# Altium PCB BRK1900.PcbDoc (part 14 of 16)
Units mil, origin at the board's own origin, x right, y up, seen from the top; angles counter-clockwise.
Board outline 8858.27 x 5905.51 mil, 10 copper layers (L1-TOP, L2-GND, L3-PWR, L4-GND, L5-PWR, L6-PWR, L7-GND, L8-SIG, L9-GND, L10-BOT), stack 48.824 mil thick; 456 components, 571 nets, 2296 pads, 2416 vias.
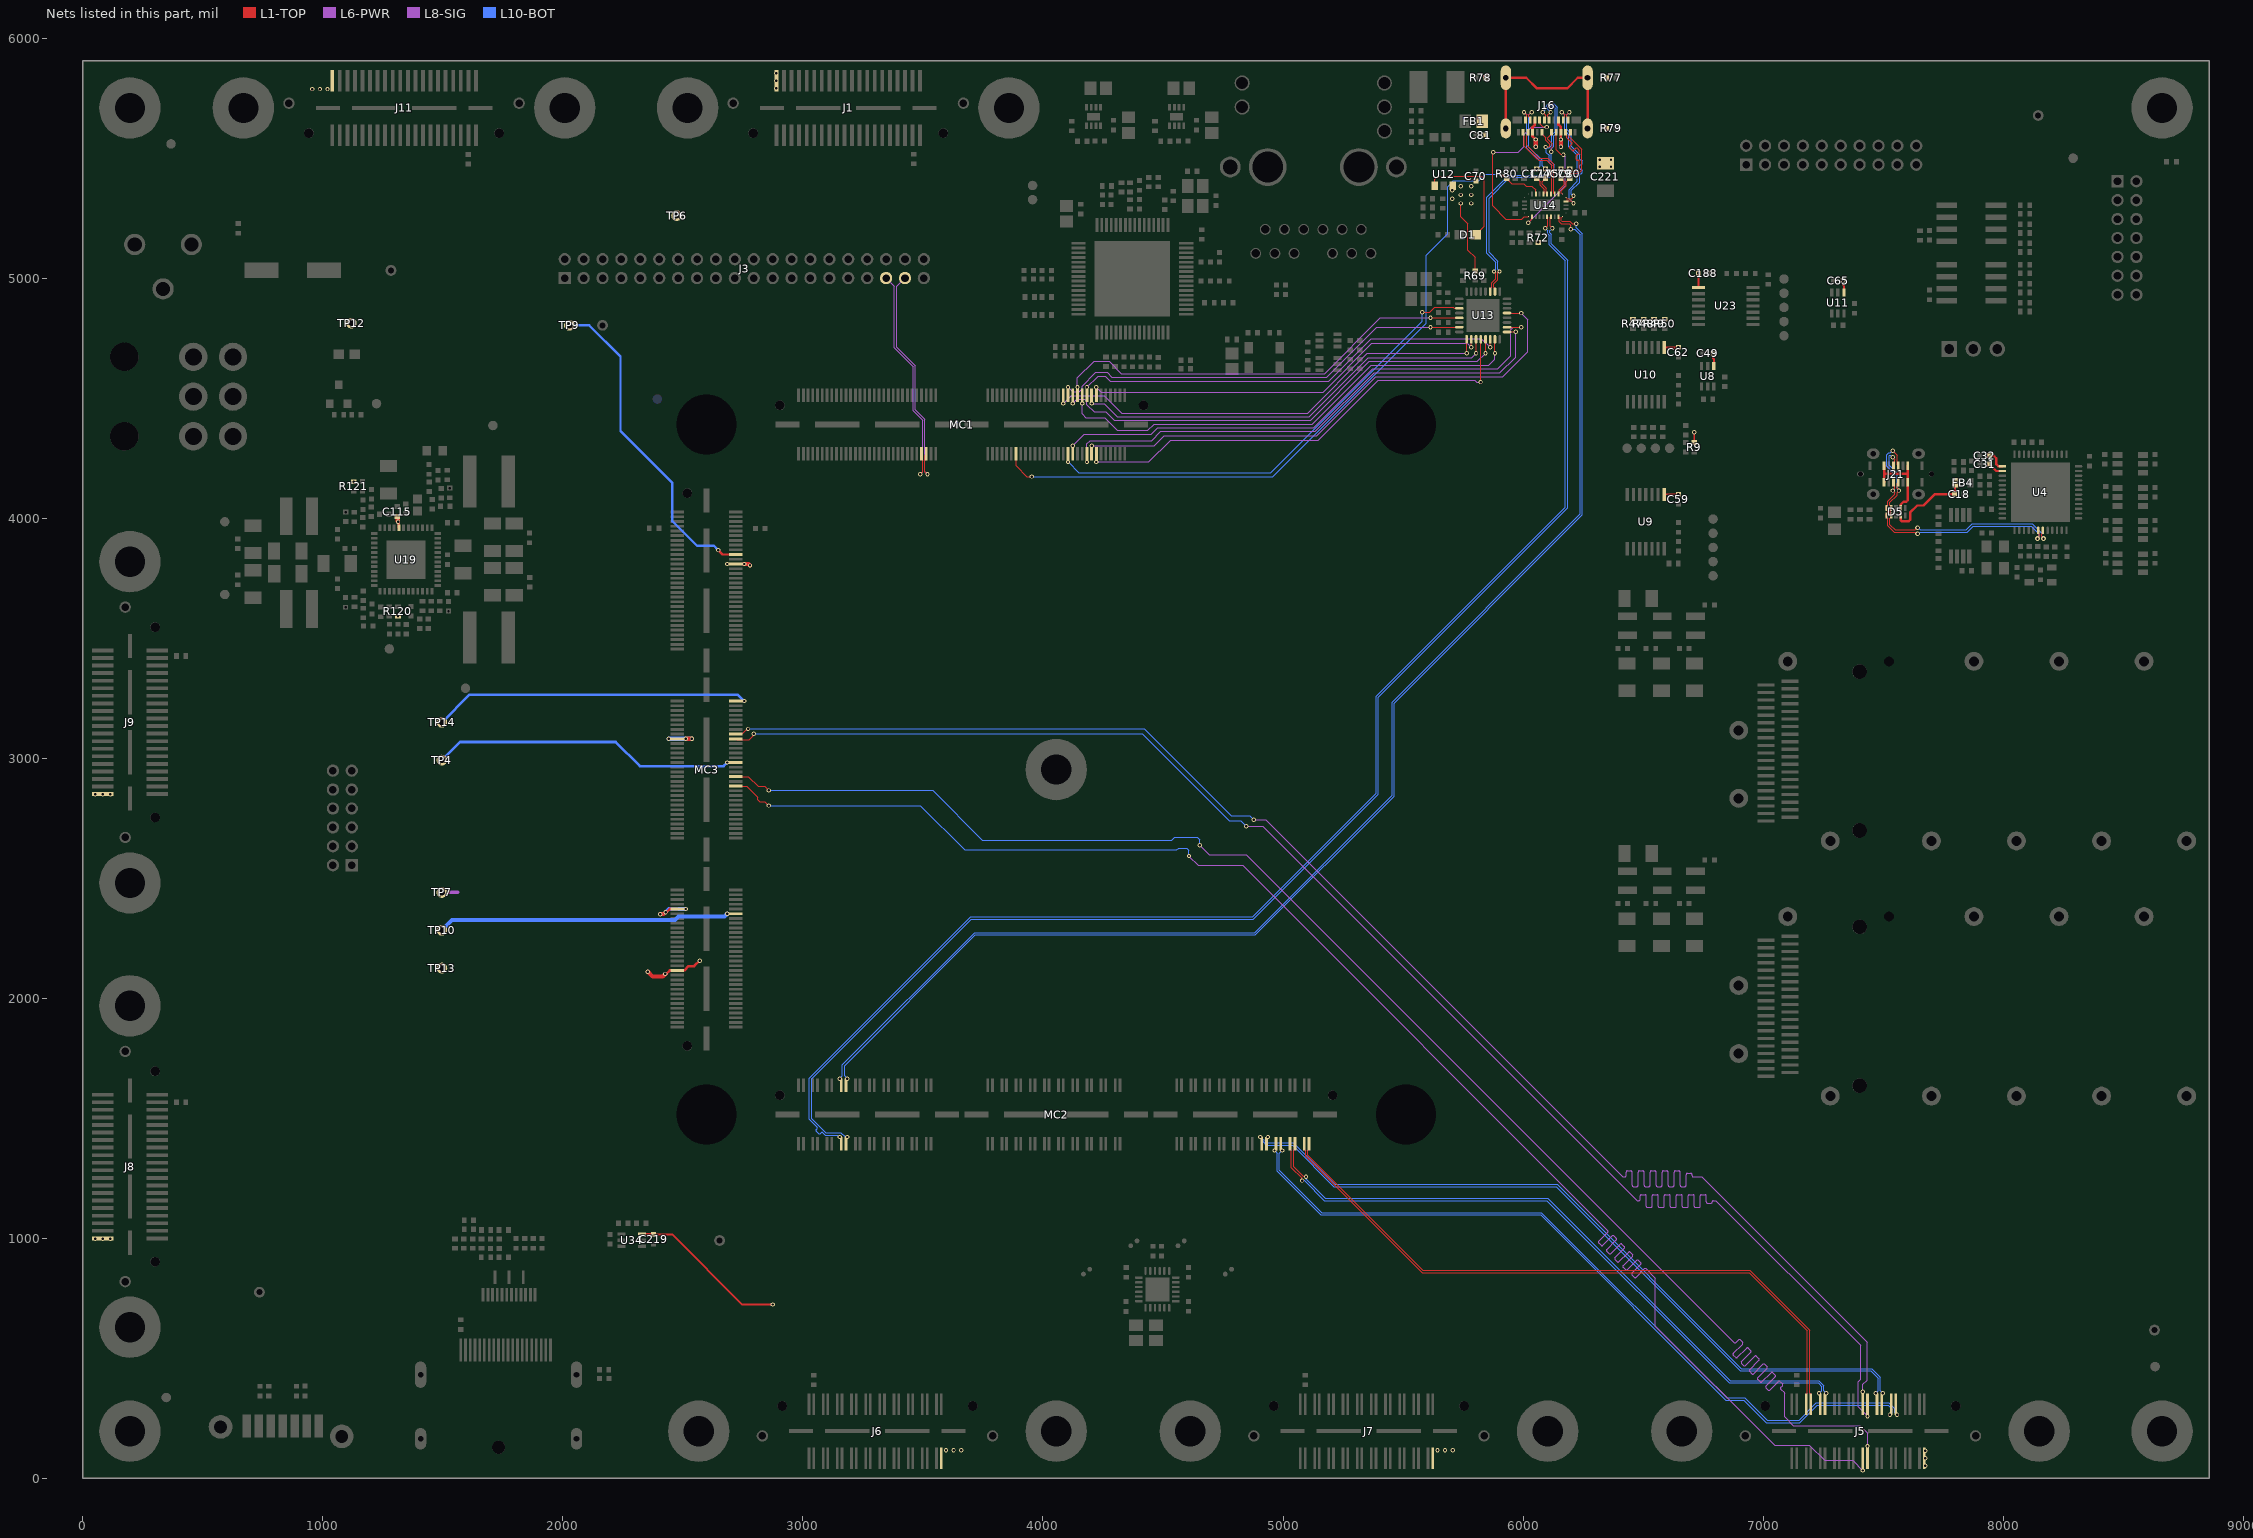
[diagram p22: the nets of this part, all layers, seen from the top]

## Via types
v1: diameter 18, hole 10, L1-TOP to L10-BOT, tented both sides, 2170 vias
v2: diameter 20, hole 10, L1-TOP to L10-BOT, tented both sides, 246 vias

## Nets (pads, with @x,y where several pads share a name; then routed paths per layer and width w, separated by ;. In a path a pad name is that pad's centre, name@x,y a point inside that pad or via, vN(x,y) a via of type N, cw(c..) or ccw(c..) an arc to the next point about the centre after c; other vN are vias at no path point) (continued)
SZG_PORTG_S6: J5.21 MC3.84 | length 6621.1
  L1-TOP w4: MC3.84@2720.08,2883.86 2765.75,2883.86 2812.48,2837.12 2812.48,2826.21 2819.36,2819.33 2841.77,2819.33 v1(2858.27,2802.83)
  L8-SIG w4: v1(4608.21,2592.58) 4647.58,2553.21 4831.88,2553.21 6334.28,1050.81 6352.66,1032.43 cw(c6349.27,1029.03) 6352.66,1025.64 6314.55,987.53 ccw(c6317.95,984.14) 6314.55,980.74 6324.74,970.56 ccw(c6328.13,973.95) 6331.52,970.56 6371.15,1010.18 cw(c6374.54,1006.79) 6377.94,1010.18 6388.12,1000 cw(c6384.72,996.61) 6388.12,993.21 6348.5,953.59 ccw(c6351.89,950.2) 6348.5,946.8 6358.68,936.62 ccw(c6362.07,940.01) 6365.47,936.62 6405.09,976.24 cw(c6408.48,972.85) 6411.88,976.24 6422.06,966.06 cw(c6418.66,962.67) 6422.06,959.27 6382.44,919.65 ccw(c6385.83,916.25) 6382.44,912.86 6392.62,902.68 ccw(c6396.01,906.07) 6399.41,902.68 6439.03,942.3 cw(c6442.42,938.91) 6445.82,942.3 6456,932.12 cw(c6452.61,928.72) 6456,925.33 6416.38,885.71 ccw(c6419.77,882.31) 6416.38,878.92 6426.56,868.74 ccw(c6429.95,872.13) 6433.35,868.74 6472.97,908.36 cw(c6476.36,904.97) 6479.76,908.36 6489.94,898.18 cw(c6486.55,894.78) 6489.94,891.39 6453.45,854.89 ccw(c6456.84,851.5) 6453.45,848.11 6463.63,837.92 ccw(c6467.02,841.32) 6470.42,837.92 6505.4,872.9 cw(c6508.79,869.51) 6512.18,872.9 6544.91,840.18 6551.18,833.91 6551.18,634.47 7047.86,137.8 7192.91,137.8 7255.91,74.8 7372.97,74.8 v1(7414.91,32.86)
  L10-BOT w4: v1(2858.27,2802.83) 3488.86,2802.83 3673.92,2617.77 4557.51,2617.77 4565.29,2625.55 4598.57,2625.55 4608.21,2615.91 v1(4608.21,2592.58)
SZG_PORTG_S7: J5.22 MC3.106 | length 6623
  L1-TOP w4: MC3.106@2720.08,3100.39 2723.98,3104.3 2749.81,3104.3 2764.88,3119.37 2768.97,3119.37 v1(2771.65,3122.05)
  L8-SIG w5: v1(4877.95,2744.09) 4926.99,2744.09 6415.17,1255.91 6421.26,1255.91 6423.76,1255.91 ccw(c6423.76,1260.91) 6428.76,1260.91 6428.76,1275.91 cw(c6433.76,1275.91) 6433.76,1280.91 6448.76,1280.91 cw(c6448.76,1275.91) 6453.76,1275.91 6453.76,1220.8 ccw(c6458.76,1220.8) 6458.76,1215.8 6473.76,1215.8 ccw(c6473.76,1220.8) 6478.76,1220.8 6478.76,1275.91 cw(c6483.76,1275.91) 6483.76,1280.91 6498.76,1280.91 cw(c6498.76,1275.91) 6503.76,1275.91 6503.76,1220.8 ccw(c6508.76,1220.8) 6508.76,1215.8 6523.76,1215.8 ccw(c6523.76,1220.8) 6528.76,1220.8 6528.76,1275.91 cw(c6533.76,1275.91) 6533.76,1280.91 6548.76,1280.91 cw(c6548.76,1275.91) 6553.76,1275.91 6553.76,1220.8 ccw(c6558.76,1220.8) 6558.76,1215.8 6573.76,1215.8 ccw(c6573.76,1220.8) 6578.76,1220.8 6578.76,1275.91 cw(c6583.76,1275.91) 6583.76,1280.91 6598.76,1280.91 cw(c6598.76,1275.91) 6603.76,1275.91 6603.76,1220.8 ccw(c6608.76,1220.8) 6608.76,1215.8 6623.76,1215.8 ccw(c6623.76,1220.8) 6628.76,1220.8 6628.76,1275.91 cw(c6633.76,1275.91) 6633.76,1280.91 6648.76,1280.91 cw(c6648.76,1275.91) 6653.76,1275.91 6653.76,1220.8 ccw(c6658.76,1220.8) 6658.76,1215.8 6673.76,1215.8 ccw(c6673.76,1220.8) 6678.76,1220.8 6678.76,1265.73 cw(c6683.76,1265.73) 6683.76,1270.73 6698.76,1270.73 cw(c6698.76,1265.73) 6703.76,1265.73 6703.76,1260.91 ccw(c6708.76,1260.91) 6708.76,1255.91 6743.94,1255.91 7433.07,566.77 7433.07,409.45 7414.91,391.29 v1(7414.91,360.84)
  L10-BOT w4: v1(2771.65,3122.05) 4421.54,3122.05 4783.37,2760.22 4861.83,2760.22 v1(4877.95,2744.09)
SZG_PORTG_S8: J5.23 MC3.88 | length 6621.1
  L1-TOP w4: MC3.88@2720.08,2923.23 2773.31,2923.23 2814.21,2882.32 2841.77,2882.32 v1(2858.27,2865.83)
  L8-SIG w4: v1(4652.75,2637.12) 4692.12,2597.75 4847.75,2597.75 6878.26,567.24 6879.68,565.82 ccw(c6883.07,569.22) 6886.46,565.82 6897.35,576.71 cw(c6900.75,573.32) 6904.14,576.71 6914.32,566.53 cw(c6910.93,563.14) 6914.32,559.74 6875.32,520.74 ccw(c6878.71,517.34) 6875.32,513.95 6885.5,503.77 ccw(c6888.9,507.16) 6892.29,503.77 6931.3,542.77 cw(c6934.69,539.38) 6938.08,542.77 6948.27,532.59 cw(c6944.87,529.2) 6948.27,525.8 6909.26,486.8 ccw(c6912.66,483.4) 6909.26,480.01 6919.44,469.83 ccw(c6922.84,473.22) 6926.23,469.83 6965.24,508.83 cw(c6968.63,505.44) 6972.02,508.83 6982.21,498.65 cw(c6978.81,495.25) 6982.21,491.86 6943.2,452.86 ccw(c6946.6,449.46) 6943.2,446.07 6953.39,435.89 ccw(c6956.78,439.28) 6960.17,435.89 6999.18,474.89 cw(c7002.57,471.5) 7005.97,474.89 7016.15,464.71 cw(c7012.75,461.31) 7016.15,457.92 6977.14,418.91 ccw(c6980.54,415.52) 6977.14,412.13 6987.33,401.94 ccw(c6990.72,405.34) 6994.11,401.94 7033.12,440.95 cw(c7036.51,437.55) 7039.91,440.95 7050.09,430.77 cw(c7046.69,427.37) 7050.09,423.98 7011.09,384.97 ccw(c7014.48,381.58) 7011.08,378.19 7021.27,368 ccw(c7024.66,371.4) 7028.06,368 7063.75,403.69 cw(c7067.14,400.3) 7070.53,403.69 7080.72,393.51 cw(c7077.32,390.12) 7080.72,386.72 7073.14,379.15 ccw(c7076.53,375.75) 7073.14,372.36 7086.92,358.58 7090.55,354.95 7090.55,255.91 7125.98,220.47 7401.57,220.47 7434.6,187.45 v1(7434.6,134.86)
  L10-BOT w4: v1(2858.27,2865.83) 3539.88,2865.83 3747.89,2657.81 4535.77,2657.81 4548.22,2670.27 4642.94,2670.27 4652.75,2660.45 v1(4652.75,2637.12)
SZG_PORTG_S9: J5.24 MC3.104 | length 6623
  L1-TOP w4: MC3.104@2720.08,3080.71 2723.58,3077.21 2775.96,3077.21 2792.6,3093.84 2792.6,3099.68 v1(2795.28,3102.36)
  L8-SIG w5: v1(4846.46,2716.54) 4915.57,2716.54 6474.63,1157.48 6480.31,1157.48 6482.82,1157.48 ccw(c6482.82,1162.48) 6487.82,1162.48 6487.82,1177.48 cw(c6492.82,1177.48) 6492.82,1182.48 6507.82,1182.48 cw(c6507.82,1177.48) 6512.82,1177.48 6512.82,1134 ccw(c6517.82,1134) 6517.82,1129 6532.82,1129 ccw(c6532.82,1134) 6537.82,1134 6537.82,1177.48 cw(c6542.82,1177.48) 6542.82,1182.48 6557.82,1182.48 cw(c6557.82,1177.48) 6562.82,1177.48 6562.82,1134 ccw(c6567.82,1134) 6567.82,1129 6582.82,1129 ccw(c6582.82,1134) 6587.82,1134 6587.82,1177.48 cw(c6592.82,1177.48) 6592.82,1182.48 6607.82,1182.48 cw(c6607.82,1177.48) 6612.82,1177.48 6612.82,1134 ccw(c6617.82,1134) 6617.82,1129 6632.82,1129 ccw(c6632.82,1134) 6637.82,1134 6637.82,1177.48 cw(c6642.82,1177.48) 6642.82,1182.48 6657.82,1182.48 cw(c6657.82,1177.48) 6662.82,1177.48 6662.82,1134 ccw(c6667.82,1134) 6667.82,1129 6682.82,1129 ccw(c6682.82,1134) 6687.82,1134 6687.82,1177.48 cw(c6692.82,1177.48) 6692.82,1182.48 6707.82,1182.48 cw(c6707.82,1177.48) 6712.82,1177.48 6712.82,1134 ccw(c6717.82,1134) 6717.82,1129 6732.82,1129 ccw(c6732.82,1134) 6737.82,1134 6737.82,1177.48 cw(c6742.82,1177.48) 6742.82,1182.48 6757.82,1182.48 cw(c6757.82,1177.48) 6762.82,1177.48 6762.82,1151.76 ccw(c6767.82,1151.76) 6767.82,1146.76 6782.82,1146.76 ccw(c6782.82,1151.76) 6787.82,1151.76 6787.82,1152.48 cw(c6792.82,1152.48) 6792.82,1157.48 6803.15,1157.48 6803.39,1157.48 7405.51,555.36 7405.51,413.39 7395.52,403.4 7395.52,297.91 v1(7434.6,258.84)
  L10-BOT w4: v1(2795.28,3102.36) 4413.39,3102.36 4776.81,2738.94 4824.05,2738.94 v1(4846.46,2716.54)
SZG_PORTG_TX0N: J5.8 MC2.120 | length 2752.4
  L1-TOP w3.3: MC2.120@5108.27,1394.09 5108.27,1371.46 5102.92,1366.11 5102.92,1345.89 5582.68,866.14 6944.88,866.14 7193.03,617.99 7193.03,354.36 7198.38,349.02 J5.8@7198.38,309.84
SZG_PORTG_TX0P: J5.6 MC2.118 | length 2752.4
  L1-TOP w3.3: MC2.118@5088.58,1394.09 5088.58,1371.46 5093.92,1366.11 5093.92,1342.17 5578.95,857.14 6941.15,857.14 7184.03,614.26 7184.03,354.36 7178.69,349.02 J5.6@7178.69,309.84
SZG_PORTG_TX1N: J5.12 MC2.116 | length 2727.7
  L1-TOP w3.3: MC2.116@5049.21,1394.09 5049.21,1371.46 5043.87,1366.11 5043.87,1298.65 5083.99,1258.53 5093.89,1258.53 v1(5095.5,1256.92)
  L10-BOT w3.3: v1@5094.55,1257.87 v1(5095.5,1256.92) 5094.49,1255.91 5094.49,1248.03 5176.04,1166.48 5669.29,1166.48 6102.15,1166.48 6862,406.64 7232.07,406.64 7252.09,386.62 7252.09,365.22 v1(7262.47,354.84)
SZG_PORTG_TX1P: J5.10 MC2.114 | length 2727.7
  L1-TOP w3.3: MC2.114@5029.53,1394.09 5029.53,1371.46 5034.87,1366.11 5034.87,1294.92 5077.62,1252.17 5077.62,1242.27 v1(5079.24,1240.65)
  L10-BOT w3.3: v1@5078.28,1241.61 v1(5079.24,1240.65) 5080.25,1241.67 5088.12,1241.67 5172.31,1157.48 5669.29,1157.48 6098.43,1157.48 6858.27,397.64 7228.35,397.64 7243.09,382.9 7243.09,365.22 v1(7232.71,354.84)
SZG_PORTG_TX2N: J5.32 MC2.112 | length 3152.6
  L10-BOT w3.3: v1(4996.06,1366.09) 4984.81,1354.85 4984.81,1282.9 5160.29,1107.43 6076.27,1107.43 6848.66,335.03 6922.77,335.03 7015.96,241.85 7149.24,241.85 7221.96,314.56 7523.77,314.56 7547.36,290.96 7547.36,274.13 7556.65,264.84 v1(7557.74,264.84)
SZG_PORTG_TX2P: J5.30 MC2.110 | length 3152.6
  L10-BOT w3.3: v1(4964.57,1366.09) 4975.81,1354.85 4975.81,1279.17 5156.56,1098.43 6072.54,1098.43 6844.93,326.03 6919.04,326.03 7012.23,232.85 7152.97,232.85 7225.68,305.56 7520.04,305.56 7538.36,287.24 7538.36,274.13 7529.08,264.84 v1(7527.98,264.84)
SZG_PORTG_TX3N: J5.28 MC2.108 | length 3062.7
  L10-BOT w3.3: v1(4937.01,1422.09) 4925.76,1410.85 4925.76,1405.51 4933.63,1397.64 5043.31,1397.64 5215.95,1225 5460.63,1225 6137.48,1225 6141.2,1225 6908.38,457.82 7452.55,457.82 7488.31,422.06 7488.31,365.22 v1(7498.69,354.84)
SZG_PORTG_TX3P: J5.26 MC2.106 | length 3062.7
  L10-BOT w3.3: v1(4905.51,1422.09) 4916.76,1410.85 4916.76,1401.78 4929.91,1388.64 5039.58,1388.64 5212.22,1216 6137.48,1216 6904.66,448.82 7448.82,448.82 7479.31,418.33 7479.31,365.22 v1(7468.93,354.84)
USB_CC1: J16.A5 U14.2 | length 494.2
  L1-TOP w5: v1(6021.41,5230.32) 6035.82,5244.74 6035.82,5254.56 U14.2@6037.26,5256 ; J16.A5@6137.8,5607.09 6137.8,5535.4 6156.73,5516.46 6165.65,5516.46 v1(6167.86,5514.25)
  L8-SIG w5: v1(6021.41,5230.32) 6176.18,5385.09 6176.18,5505.93 v1(6167.86,5514.25)
USB_CC2: J16.B5 U14.1 | length 746.2
  L1-TOP w5: v1(5876,5524) 5872.61,5520.61 5872.61,5300.39 5927.01,5245.99 5995.08,5245.99 6005.09,5256 U14.1@6021.51,5256 ; J16.B5@6068.9,5658.27 6072.3,5654.86 6072.3,5639.97 6082.43,5629.85 6097.71,5629.85 v1(6098.46,5629.1)
  L8-SIG w5: v1(5876,5524) 5979,5524 6003,5548 6003,5598 6034.1,5629.1 v1(6098.46,5629.1)
USB_CLKOUT: MC1.93 U13.1 | length 1885.1
  L1-TOP w4.55: v1(5764.65,4686.28) U13.1@5764.65,4745.06
  L8-SIG w4.05: v1(4084.65,4477.42) 4117.15,4509.92 4256.08,4509.92 4328.29,4437.71 5102.59,4437.71 5351.16,4686.28 v1(5764.65,4686.28)
USB_DATA0: MC1.105 U13.3 | length 1792.1
  L1-TOP w4.55: v1(5804.02,4686.28) U13.3@5804.02,4745.06
  L8-SIG w4.05: v1(4202.76,4477.42) 4254.58,4477.42 4309.53,4422.47 5108.9,4422.47 5353.99,4667.56 5785.3,4667.56 v1(5804.02,4686.28)
USB_DATA1: MC1.108 U13.4 | length 1923.4
  L1-TOP w4.55: v1(5822.83,4566.93) 5823.27,4567.37 5823.27,4744.62 U13.4@5823.71,4745.06
  L8-SIG w4.05: v1(4222.44,4234.11) 4441.11,4234.11 4531.31,4324.31 5145.78,4324.31 5396.41,4574.94 5799.07,4574.94 5807.09,4566.93 v1(5822.83,4566.93)
USB_DATA2: MC1.97 U13.5 | length 1945
  L1-TOP w4.55: v1(5843.39,4686.28) U13.5@5843.39,4745.06
  L8-SIG w4.05: v1(4124.02,4477.42) 4141.4,4494.8 4174.76,4494.8 4183,4486.56 4183,4472.64 4212.64,4443 4261,4443 4296.3,4407.7 5115.02,4407.7 5360.11,4652.78 5809.9,4652.78 v1(5843.39,4686.28)
USB_DATA3: MC1.103 U13.6 | length 1830.4
  L1-TOP w4.55: v1(5863.08,4711.28) U13.6@5863.08,4745.06
  L8-SIG w4.05: v1(4183.07,4545.42) 4229.65,4592 4258.39,4592 4279.53,4570.87 5189.34,4570.87 5366.51,4748.03 5826.32,4748.03 v1(5863.08,4711.28)
USB_DATA4: MC1.101 U13.7 | length 1996
  L1-TOP w4.55: v1(5882.76,4686.28) U13.7@5882.76,4745.06
  L8-SIG w4.05: v1(4163.39,4477.42) 4163.39,4434.6 4178.99,4419 4257,4419 4309.86,4366.14 4437.14,4366.14 4463,4392 5121.52,4392 5366.61,4637.08 5857.56,4637.08 5882.76,4662.29 v1(5882.76,4686.28)
USB_DATA5: MC1.104 U13.9 | length 2151.6
  L1-TOP w4.55: U13.9@5932.96,4775.57 5968.17,4775.57 v1(5968.74,4776.13)
  L8-SIG w4.05: v1(4183.07,4234.11) 4183.07,4309.07 4196.43,4322.43 4453,4322.43 4491.57,4361 5134.36,4361 5379.45,4606.08 5903.65,4606.08 5968.74,4671.18 v1(5968.74,4776.13)
USB_DATA6: MC1.98 U13.10 | length 2194.3
  L1-TOP w4.55: U13.10@5932.96,4795.25 v1(5991.74,4795.25)
  L8-SIG w4.05: v1(4124.02,4302.11) 4170.9,4349 4451,4349 4479,4377 5127.74,4377 5372.82,4622.08 5893.67,4622.08 5948.82,4677.23 5948.82,4785.62 5958.45,4795.25 v1(5991.74,4795.25)
USB_DATA7: MC1.106 U13.13 | length 2210.5
  L1-TOP w4.55: U13.13@5932.96,4854.31 v1(5991.74,4854.31)
  L8-SIG w4.05: v1(4202.76,4302.11) 4463,4302.11 4504.89,4344 5141.4,4344 5386.49,4589.08 5915.79,4589.08 6019.69,4692.98 6019.69,4826.36 v1(5991.74,4854.31)
USB_DIR: MC1.95 U13.31 | length 1773.3
  L1-TOP w4.55: v1(5614.14,4795.25) U13.31@5734.14,4795.25
  L8-SIG w4.05: v1(4104.33,4545.42) 4123.75,4526 4151,4526 4163,4538 4163,4550 4220,4607 4267.02,4607 4287.4,4586.61 5181.47,4586.61 5390.11,4795.25 v1(5614.14,4795.25)
USB_DN: J16.A7 J16.B7 U13.19 | length 1230.6
  L1-TOP w4.05: U13.19@5863.08,4943.87 5863.08,4955.68 5868.42,4961.02 5868.42,4979.57 5885.83,4996.98 5885.83,5023.62 5881.89,5027.56 v1(5878.83,5027.56) ; J16.A7@6078.74,5607.09 6078.74,5599.99 6093.93,5584.81 6093.93,5574.08 6108,5560 6111.51,5556.49 6111.51,5548.49 6109.11,5546.1 v1(6093.48,5546.1) ; J16.B7@6108.27,5658.27 6108.27,5666.12 6102.93,5671.46 6102.93,5679.55 v1(6114.41,5691.04)
  L10-BOT w4.05: v1(5878.83,5027.56) 5878.83,5029.91 5885.83,5036.91 5885.83,5066.93 5849,5103.76 5849,5307.08 5849,5336.09 5940.91,5428 6106,5428 6120,5442 6120,5469.33 6108.48,5480.86 6108.48,5510.79 6096.48,5522.79 6096.48,5543.1 6109.11,5543.1 6119.5,5553.49 6119.5,5596.5 6133,5610 6133,5708 6123.52,5717.48 6108.95,5717.48 6102.48,5711 6102.48,5702.98 v1(6114.41,5691.04)
USB_DP: J16.A6 J16.B6 U13.18 | length 1248.1
  L1-TOP w4.05: U13.18@5882.76,4943.87 5882.76,4955.9 5877.42,4961.24 5877.42,4975.85 5894.83,4993.25 5894.83,5023.62 5898.76,5027.56 v1(5901.83,5027.56) ; v1(6081.54,5691.04) 6093.93,5678.66 6093.93,5671.26 6088.58,5665.91 J16.B6@6088.58,5658.27 ; v1(6117.48,5526.1) 6117.48,5541.74 6117.87,5542.13 6120.51,5544.77 6120.51,5560.22 6117.87,5562.86 6102.93,5577.8 6102.93,5584.15 6118.11,5599.33 J16.A6@6118.11,5607.09
  L10-BOT w4.05: v1(5901.83,5027.56) 5901.83,5029.91 5894.83,5036.91 5894.83,5070.66 5858,5107.48 5858,5255.53 5858,5332.37 5944.63,5419 6109.73,5419 6112.36,5421.64 6129,5438.27 6129,5473.06 6117.48,5484.58 v1(6117.48,5526.1) 6117.48,5538.74 6128.5,5549.76 6128.5,5592.77 6142,5606.27 6142,5711.73 6127.25,5726.48 6105.23,5726.48 6093.48,5714.73 6093.48,5702.98 v1(6081.54,5691.04)
USB_JTAG_DN: D5.5 D5.6 J21.A7 J21.B7 U4.6 | length 1213.9
  L1-TOP w4: v1(7539.45,4280.49) 7557.77,4262.18 7557.77,4235.4 7558.71,4234.46 7558.71,4221.83 J21.B7@7562.61,4217.93 ; J21.A7@7542.93,4149.82 7546.83,4145.91 7546.83,4133.29 7547.77,4132.35 7547.77,4124.27 7540.11,4116.61 7539.45,4116.61 7539.45,4113.59 7547.45,4105.59 7547.45,4099.28 7518.24,4070.07 7518.24,4053.87 7513.4,4049.03 7513.4,4034.27 7518.23,4029.44 7518.24,4023.35 7513.4,4018.52 7513.4,4003.76 7518.24,3998.91 7518.24,3969.11 7545.19,3942.16 7632.98,3942.16 7640.48,3934.66 v2(7643.32,3934.66) ; v2(8142.54,3914.8) 8142.54,3917.64 8150.13,3925.23 8150.13,3933.33 8145.29,3938.18 U4.6@8145.29,3949.42
  L10-BOT w4: v1(7539.45,4114.93) 7539.45,4116.27 7547.45,4124.27 7547.45,4182.41 7514.4,4215.47 7514.4,4263.79 7522.6,4271.99 7530.11,4271.99 7538.61,4280.49 v1(7539.45,4280.49) ; v2(7643.32,3934.66) 7646.17,3934.66 7653.67,3942.16 7850.79,3942.16 7874.88,3966.26 8116.54,3966.26 8150.04,3932.76 8150.04,3925.14 8142.54,3917.64 v2(8142.54,3914.8)
USB_JTAG_DP: D5.4 D5.7 J21.A6 J21.B6 U4.7 | length 1165.4
  L1-TOP w4: v1(7539.45,4253.49) 7539.45,4252.47 7547.77,4244.15 7547.77,4235.4 7546.83,4234.46 7546.83,4221.83 J21.B6@7542.93,4217.93 ; J21.A6@7562.61,4149.82 7558.71,4145.91 7558.71,4133.29 7557.77,4132.35 7557.77,4124.27 7565.45,4116.59 7565.45,4113.59 7557.45,4105.59 7557.45,4095.13 7528.24,4065.93 7528.24,4053.87 7533.09,4049.03 7533.09,4034.27 7528.26,4029.44 7528.24,4023.35 7533.09,4018.52 7533.09,4003.76 7528.24,3998.91 7528.24,3973.25 7549.33,3952.16 7632.98,3952.16 7640.48,3959.66 v2(7643.32,3959.66) ; U4.7@8164.98,3949.42 8164.98,3938.18 8160.13,3933.33 8160.13,3925.14 8167.54,3917.73 v2(8167.54,3914.8)
  L10-BOT w4: v1(7539.45,4253.49) 7538.61,4253.49 7530.11,4261.99 7526.74,4261.99 7524.4,4259.65 7524.4,4219.61 7557.45,4186.56 7557.45,4124.27 7565.45,4116.27 v1(7565.45,4114.93) ; v2(7643.32,3959.66) 7646.17,3959.66 7653.67,3952.16 7846.64,3952.16 7870.74,3976.26 8120.69,3976.26 8160.04,3936.9 8160.04,3925.14 8167.54,3917.64 v2(8167.54,3914.8)
USB_NXT: MC1.107 U13.2 | length 1695.4
  L1-TOP w4.55: v1(5784.34,4711.28) U13.2@5784.34,4745.06
  L8-SIG w4.05: v1(4222.44,4545.42) 4242.86,4525 5166.81,4525 5370.16,4728.35 5767.27,4728.35 v1(5784.34,4711.28)
USB_RESET_B: MC1.96 U13.27 | length 1959.4
  L1-TOP w4.55: v1(5579.71,4858.28) 5611.48,4858.28 5632.61,4879.41 5708.61,4879.41 5714.02,4873.99 U13.27@5734.14,4873.99
  L10-BOT w4.55: v1(4104.33,4234.11) 4149.44,4189 4949.19,4189 5579.71,4819.52 v1(5579.71,4858.28)
USB_SHELL: C81.2 FB1.1 J16.M1 J16.M2 J16.M3 J16.M4 R77.1 R78.1 R79.1 | length 798.8
  L1-TOP w10: J16.M2@5928.35,5623.23 J16.M3@5928.35,5834.25 6013.08,5834.25 6057.23,5790.1 6183.55,5790.1 6227.7,5834.25 J16.M4@6268.5,5834.25 J16.M1@6268.5,5623.23
USB_SSRX_N: MC2.15 U14.10 | length 5617.3
  L1-TOP w4.05: U14.10@6163.24,5256 6159.87,5252.63 6159.87,5239 6162.87,5236 6195.05,5236 6203.02,5228.02 6205.36,5225.68 v1(6221.69,5225.68)
  L10-BOT w4.05: v1(3185.04,1665.4) 3173.79,1676.65 3173.79,1719 3718.57,2263.78 4884.85,2263.78 5463.02,2841.95 5463.02,3229.81 6247,4013.8 6247,5184.05 6221.69,5209.36 v1(6221.69,5225.68)
USB_SSRX_P: MC2.13 U14.9 | length 5617.3
  L1-TOP w4.05: U14.9@6147.5,5256 6150.87,5252.63 6150.87,5235.27 6159.14,5227 6191.32,5227 6199,5219.32 v1(6199,5203)
  L10-BOT w4.05: v1(3153.54,1665.4) 3164.79,1676.65 3164.79,1722.73 3714.84,2272.78 4881.12,2272.78 5454.02,2845.67 5454.02,3233.54 6238,4017.53 6238,5180.32 6215.32,5203 v1(6199,5203)
USB_SSRXN1: J16.B10 U14.14 | length 503.9
  L1-TOP w4.05: v1(6161.02,5691.04) 6172.67,5679.4 6172.67,5671.67 6167.32,5666.33 J16.B10@6167.32,5658.27 ; U14.14@6178.99,5318.99 6182.37,5322.37 6199.77,5322.37 v1(6210.05,5312.09)
  L10-BOT w4.05: v1(6161.02,5691.04) 6172.46,5679.6 6172.46,5615.81 6190.64,5597.64 6190.64,5546.36 6226,5511 6226,5402.73 6192,5368.73 6192,5330.14 v1(6210.05,5312.09)
USB_SSRXN2: J16.A10 U14.18 | length 327.7
  L1-TOP w4.05: J16.A10@6019.69,5607.09 6019.69,5598.83 6014.34,5593.49 6014.34,5553.66 6067.96,5500.04 6102.52,5500.04 6128.37,5474.19 6128.37,5353.86 U14.18@6131.75,5350.49
USB_SSRXP1: J16.B11 U14.15 | length 501.8
  L1-TOP w4.05: U14.15@6178.99,5334.74 6182.37,5331.37 6201.76,5331.37 v1@6210.05,5339.65 ; J16.B11@6187.01,5658.27 6187.01,5666.25 6181.67,5671.6 6181.67,5679.81 v1(6192.89,5691.04)
  L10-BOT w4.05: v1(6192.89,5691.04) 6181.46,5679.6 6181.46,5619.54 6197,5604 6199.64,5601.36 6199.64,5550.09 6235,5514.73 6235,5502 6235,5495.85 6238.81,5492.04 6243.19,5492.04 6247,5488.23 6247,5476.8 6243.19,5472.99 6238.81,5472.99 6235,5469.18 6235,5457.75 6238.81,5453.94 6243.19,5453.94 6247,5450.13 6247,5438.7 6243.19,5434.89 6238.81,5434.89 6235,5431.08 6235,5410 6235,5399 6201,5365 6201,5348.69 v1@6210.05,5339.65
  other v1: 6210.05,5342.65
USB_SSRXP2: J16.A11 U14.19 | length 327.7
  L1-TOP w4.05: J16.A11@6000,5607.09 6000,5598.96 6005.34,5593.62 6005.34,5549.93 6055.27,5500 6064.23,5491.04 6098.79,5491.04 6119.37,5470.46 6119.37,5353.86 U14.19@6116,5350.49
USB_SSTX_N: MC2.16 U14.7 | length 5969.5
  L1-TOP w4.05: U14.7@6116,5256 6112.63,5252.63 6112.63,5215.37 v1@6121,5207
  L10-BOT w4.05: v1(3185.04,1422.09) 3182.37,1424.76 3173.54,1424.76 3158.6,1439.7 3095.3,1439.7 3036,1499 3036,1664 3702,2330 4876.73,2330 5397,2850.27 5397,3254.35 6185,4042.35 6185,5075 6117,5143 6117,5182.63 6111.72,5187.91 6111.72,5196.62 6121,5205.9 v1@6121,5207
  other v1: 6122.1,5207
USB_SSTX_P: MC2.14 U14.6 | length 5969.5
  L1-TOP w4.05: v1@6093.44,5207 6103.63,5217.19 6103.63,5252.63 U14.6@6100.25,5256
  L10-BOT w4.05: v1(3153.54,1422.09) 3151.22,1422.09 3143.32,1430 3092.27,1430 3083.97,1438.3 3082.54,1439.73 ccw(c3079.14,1436.33) 3075.74,1439.73 3072.7,1436.7 cw(c3069.3,1440.1) 3065.9,1436.7 3055.7,1446.9 cw(c3059.1,1450.31) 3055.7,1453.71 3058.73,1456.74 ccw(c3055.33,1460.14) 3058.73,1463.54 3043.8,1478.48 3042.36,1479.91 3036.64,1485.64 3027,1495.27 3027,1667.73 3698.27,2339 4873,2339 5388,2854 5388,3258.08 6176,4046.08 6176,5071.27 6108,5139.27 6108,5178.9 6102.72,5184.18 6102.72,5196.62 6093.44,5205.9 v1@6093.44,5207
  other v1: 6092.34,5207
USB_SSTXN1: C80.2 J16.A3 | length 281.2
  L1-TOP w4.05: J16.A3@6177.17,5607.09 6177.17,5598.97 6182.51,5593.63 6182.51,5584.49 6190.59,5576.41 6192.02,5574.98 6202.75,5564.25 cw(c6199.35,5560.85) 6202.75,5557.45 6193.88,5548.58 ccw(c6197.28,5545.18) 6193.88,5541.77 6204.08,5531.57 ccw(c6207.48,5534.97) 6210.88,5531.57 6219.75,5540.44 cw(c6223.15,5537.04) 6226.56,5540.44 6227.99,5539.01 6234.78,5532.22 6234.78,5527.56 6234.78,5519.95 cw(c6229.97,5519.95) 6229.97,5515.14 6226.04,5515.14 ccw(c6226.04,5510.33) 6221.23,5510.33 6221.23,5495.9 ccw(c6226.04,5495.9) 6226.04,5491.09 6229.97,5491.09 cw(c6229.97,5486.28) 6234.78,5486.28 6234.78,5484.25 6234.78,5452.5 6227.59,5445.3 6204.37,5445.3 6194.59,5455.08 v1(6194,5455.08)
USB_SSTXN1_C: C80.1 U14.16 | length 80
  L1-TOP w4.05: U14.16@6163.24,5350.49 6159.87,5353.86 6159.87,5364 6180.5,5384.63 6180.5,5401.42 C80.1@6194,5414.92
USB_SSTXN2: C175.2 J16.B3 | length 308.9
  L1-TOP w4.05: J16.B3@6029.53,5658.27 6029.53,5666.37 6024.19,5671.71 6024.19,5679.81 v1(6035.41,5691.04)
  L10-BOT w4.05: v1(6035.41,5691.04) 6023.98,5679.6 6023.98,5545.33 6079.5,5489.81 6079.5,5468.58 v1(6093,5455.08)
USB_SSTXN2_C: C175.1 U14.20 | length 78.6
  L1-TOP w4.05: C175.1@6093,5414.92 6079.5,5401.42 6079.5,5390.89 6096.88,5373.51 6096.88,5369.73 6096.88,5353.86 U14.20@6100.25,5350.49
USB_SSTXP1: C79.2 J16.A2 | length 281.3
  L1-TOP w4.05: v1(6158,5455.08) 6158.59,5455.08 6166.8,5446.87 6166.8,5446.28 6176.78,5436.3 6231.32,5436.3 6243.78,5448.77 6243.78,5458.06 6243.78,5464.33 6243.78,5530.94 6243.78,5535.94 6191.51,5588.22 6191.51,5593.39 6196.85,5598.73 J16.A2@6196.85,5607.09
USB_SSTXP1_C: C79.1 U14.17 | length 80
  L1-TOP w4.05: U14.17@6147.5,5350.49 6150.87,5353.86 6150.87,5367.73 6171.5,5388.36 6171.5,5401.42 C79.1@6158,5414.92
USB_SSTXP2: C174.2 J16.B2 | length 309.1
  L1-TOP w4.05: v1(6003.54,5691.04) 6015.19,5679.4 6015.19,5671.84 6009.84,5666.49 J16.B2@6009.84,5658.27
  L10-BOT w4.05: v1(6003.54,5691.04) 6014.98,5679.6 6014.98,5545.29 6014.98,5541.6 6070.5,5486.08 6070.5,5468.58 v1(6057,5455.08)
USB_SSTXP2_R: C174.1 U14.21 | length 78.6
  L1-TOP w4.05: C174.1@6057,5414.92 6070.5,5401.42 6070.5,5387.16 6087.88,5369.78 6087.88,5353.86 U14.21@6084.5,5350.49
USB_STP: MC1.99 U13.29 | length 1775.6
  L1-TOP w4.55: v1(5614.14,4834.62) U13.29@5734.14,4834.62
  L8-SIG w4.05: v1(4143.7,4545.42) 4143.7,4584.7 4212.54,4653.54 4275.59,4653.54 4326.77,4602.36 5173.23,4602.36 5405.49,4834.62 v1(5614.14,4834.62)
USB_TYPEC_INT_B: MC1.74 R80.1 U14.23 | length 3080.3
  L1-TOP w5: MC1.74@3887.79,4268.11 3887.79,4218.5 3933.07,4173.23 v1(3952.76,4173.23) ; v1(5905.51,5433.07) 5908,5430.58 5913.5,5430.58 5929.67,5414.4 5931.64,5414.4 5953.05,5393 6003.25,5393 6013,5383.25 6036.75,5383.25 6053.01,5366.99 U14.23@6053.01,5350.49
  L10-BOT w5: v1(3952.76,4173.23) 4956.69,4173.23 5595.66,4812.2 5595.66,5095.66 5685.04,5185.04 5685.04,5381.29 5709.69,5405.94 5815.38,5405.94 5842.52,5433.07 v1(5905.51,5433.07)
USB_VBUS: C70.2 C221.2 J16.A4 J16.A9 J16.B4 J16.B9 R69.1 R72.2 U12.6 | length 541.9
  L1-TOP w5: v1(5740.16,5311.02) 5740.16,5255.91 5769.68,5226.38 5769.68,5116.14 5800.02,5085.81 R69.1@5800.02,5029.96
  L1-TOP w11: J16.B4@6049.21,5658.27 6049.21,5638.48 6039.37,5628.64 J16.A9@6039.37,5607.09 6039.37,5590.55 v1(6052.82,5577.1) ; J16.B9@6147.64,5658.27 6147.64,5638.94 6157.48,5629.1 J16.A4@6157.48,5607.09 v1(6157.48,5577.1)
  L1-TOP w18: v1(6052.82,5547.1) v1(6052.82,5577.1) ; v1(6157.48,5547.1) v1(6157.48,5577.1)
  other v1: 6062.41,5148.64 5783.46,5311.02 5704.72,5330.71 5740.16,5346.46 5783.46,5346.46 5704.72,5366.14 5740.16,5381.89 5783.46,5381.89 6318.9,5464.57 6366.14,5464.57 6318.9,5492.13 6366.14,5492.13
VBUS_C: C18.2 D5.2 D5.9 FB4.2 J21.A4 J21.A9 J21.B4 J21.B9 | length 751.2
  L1-TOP w10: J21.A9@7503.56,4149.82 7503.56,4184.26 ; J21.B4@7503.56,4217.93 7503.56,4184.26 ; J21.B9@7601.98,4217.93 7601.98,4183.87 ; FB4.2@7801.59,4147.26 7799.03,4144.7 7799.03,4102.57 C18.2@7796.47,4100.01 7715.15,4100.01 7667.91,4052.77 7641.57,4052.77 7611.96,4023.16 7611.96,3993.22 7605.17,3986.43 7578.71,3986.43 7572.46,3992.69 D5.9@7572.46,4011.14 7572.46,4055.86 7585.12,4068.52 7596.13,4068.52 7601.98,4074.38 J21.A4@7601.98,4149.82 7601.98,4183.87 ; 7503.56,4184.26 7601.59,4184.26 7601.98,4183.87
VBUS_FAULT: D1.1 U12.4 | length 492.8
  L1-TOP w5: U12.4@5631.89,5383.86 5631.89,5411.42 5645.67,5425.2 5826.77,5425.2 5838.59,5413.38 5838.59,5215.13 D1.1@5803.46,5180
VCC_PSBATT: MC3.120 TP14.1 | length 1317.9
  L10-BOT w11: TP14.1@1496.06,3149.61 1611.46,3265 2728.27,3265 v1(2755.08,3238.19)
VCCA: C32.2 U4.37 | length 85.9
  L1-TOP w10: C32.2@7942.93,4260.45 7959.27,4260.45 7970.09,4249.62 7970.09,4226 7979.94,4216.16 U4.37@7996.67,4216.16
VCCO_28: J1.39 J7.39 MC3.158 TP6.1 | length 26.9
  L1-TOP w18: v1(2755.08,3809.06) 2773.62,3809.06 v1(2779.53,3803.15)
  other v1: 5643.24,118 5674.74,118 5706.24,118 2685.08,3809.06 2888.58,5789.97 2888.58,5821.46 2888.58,5852.96
VCCO_67: C219.2 J6.39 J11.39 MC3.103 TP12.1 U34.6 | length 786.9
  L1-TOP w8: U34.6@2330.71,1018.11 2331.5,1017.32 2377.17,1017.32 C219.2@2377.95,1016.54 2455.91,1016.54 2748.03,724.41 v1(2874.02,724.41)
  L1-TOP w18: v1(2511.77,3080.71) 2537.67,3080.71 v1(2537.72,3080.76)
  L10-BOT w18: v1(2441.77,3080.71) v1(2511.77,3080.71) 2537.67,3080.71 v1(2537.72,3080.76)
  other v1: 3596,118 3627.5,118 3659,118 956.71,5787.32 988.21,5787.32 1019.71,5787.32
VCCO_68: J5.39 J9.39 MC3.51 TP7.1 | length 262.4
  L1-TOP w11: v1(2428.01,2358.73) 2432.73,2358.73 2446.05,2372.05 MC3.51@2476.77,2372.05
  L1-TOP w15: v1(2405.51,2350.39) 2406.09,2350.97 2419.43,2350.97 2427.19,2358.73 v1(2428.01,2358.73)
  L6-PWR w15: TP7.1@1496.06,2440.94 1562.99,2440.94
  L10-BOT w15: v1(2405.51,2350.39) 2418.86,2350.39 2427.19,2358.73 v1(2428.01,2358.73) 2441.32,2372.05 v1(2511.77,2372.05)
  other v1: 7674.82,52.36 7674.82,83.86 7674.82,115.35 52.55,2849.21 84.05,2849.21 115.55,2849.21
VCCO_87_88: C49.2 C59.2 C62.2 C65.2 C188.2 J8.39 MC3.25 R9.2 R47.2 R48.2 R49.2 R50.2 TP13.1 U8.1 U9.1 U10.1 U11.1 U23.1 | length 575.4
  L1-TOP w7: R9.2@6712.6,4314.96 v1(6712.6,4358.27)
  L1-TOP w8: U10.1@6588.05,4711.19 v1(6646.59,4711.19) ; U9.1@6588.41,4099.61 v1(6646.94,4099.61) ; U23.1@6730.74,4960.52 C188.2@6730.74,5019.06 ; v1(6789.98,4685.95) 6789.98,4666.87 6794.49,4662.36 U8.1@6794.49,4634.26 ; v1(7332.1,4989.67) 7332.1,4971.59 7336.61,4967.08 U11.1@7336.61,4939.98
  L1-TOP w10: v1(2426.79,2101.45) 2428.33,2102.98 2432.98,2102.98 2446.14,2116.14 2506.14,2116.14 2524,2134 2547,2134 v1(2570,2157)
  L1-TOP w18: v1(2354.33,2110.24) 2374.02,2090.55 2415.89,2090.55 v1(2426.79,2101.45)
  other v1: 52.55,998.81 84.05,998.81 115.55,998.81 6457.68,4828.74 6501.97,4828.74 6545.52,4828.74 6589.57,4828.74 6730.11,5019.68
VCORE: C31.2 U4.38 | length 65.9
  L1-TOP w10: C31.2@7942.93,4225.01 7942.93,4224.42 7970.88,4196.47 U4.38@7996.67,4196.47
VDDD: C115.2 R120.2 R121.2 U19.20 | length 51.1
  L1-TOP w11: v1(1313.58,3985.64) 1313.58,3983.74 1316.65,3980.68 1316.65,3959.93 U19.20@1317.06,3959.53
  L1-TOP w18: C115.2@1310.58,4007.56 1311.17,4007.56 1312.41,4006.32 1312.41,3986.81 v1(1313.58,3985.64)
  other v1: 1313.29,3591.84 1129,4151.68
VREF_28: MC3.162 TP9.1 | length 1363.1
  L1-TOP w10: v1(2647,3867) 2665.57,3848.43 MC3.162@2720.08,3848.43
  L10-BOT w10: TP9.1@2027.56,4803.15 2110.24,4803.15 2240.16,4673.23 2240.16,4362.64 2456.43,4146.37 2456.43,3987.22 2558.65,3885 2629,3885 v1(2647,3867)
VREF_67: MC3.94 TP4.1 | length 1268.3
  L10-BOT w11: TP4.1@1496.06,2992.13 1571.53,3067.59 2219.81,3067.59 2320.4,2967 2669.79,2967 v1(2685.08,2982.28)
VREF_68: MC3.50 TP10.1 | length 1217.6
  L10-BOT w18: TP10.1@1496.06,2283.46 1538.6,2326 2467,2326 2482,2341 2673.72,2341 v1(2685.08,2352.36)
XADC_VN: J3.37 MC1.56 | length 975.2
  L1-TOP w3.3: MC1.56@3513.78,4268.11 3510.2,4264.53 3510.2,4241.56 3508.44,4239.8 3508.44,4192.39 v1@3517.72,4183.11
  L8-SIG w3.15: J3.37@3425.2,5000 3390.33,4965.13 3390.33,4712.67 3468,4635 3468,4452 3508.44,4411.56 3508.44,4192.39 v1@3517.72,4183.11
  other v1: 3518.82,4183.11
XADC_VP: J3.35 MC1.54 | length 975.2
  L1-TOP w3.3: v1@3490.16,4183.11 3499.44,4192.39 3499.44,4240.16 3494.09,4245.5 MC1.54@3494.09,4268.11
  L8-SIG w3.15: J3.35@3346.46,5000 3381.33,4965.13 3381.33,4708.95 3459,4631.27 3459,4448.27 3499.44,4407.84 3499.44,4192.39 v1@3490.16,4183.11
  other v1: 3489.06,4183.11
pads on no net: FID1.FID? FID2.FID? FID3.FID? FID4.FID? FID5.FID? FID6.FID? FID7.FID? FID8.FID? J1.1@2519.69,5708.66 J1.1@3858.27,5708.66 J1.37 J1.38 J1.MH J2.12 J5.1@6660.63,196.85 J5.1@8149.61,196.85 J5.37 J5.38 J5.MH J6.1@2566.14,196.85 J6.1@4055.12,196.85 J6.37 J6.38 J6.MH J7.1@4613.39,196.85 J7.1@6102.36,196.85 J7.37 J7.38 J7.MH J8.1@196.85,629.92 J8.1@196.85,1968.5 J8.37 J8.38 J8.MH J9.1@196.85,2480.32 J9.1@196.85,3818.9 J9.37 J9.38 J9.MH J11.1@669.29,5708.66 J11.1@2007.87,5708.66 J11.37 J11.38 J11.MH J12.MH J14.MH J15.MH J16.A8 J16.B8 J18.3 J19.0 J20.7 J20.9 J20.10 J20.12 J20.M1 J21.A8 J21.B8 J21.M5 J21.M6 JSO1.1 JSO2.1 JSO3.1 JSO4.1 MC1.14 MC1.21 MC1.28 MC1.49 MC1.51 MC1.52 MC1.110 MC1.MH MC2.2 MC2.4 MC2.5 MC2.6 MC2.7 MC2.8 MC2.9 MC2.11 MC2.21 MC2.23 MC2.25 MC2.27 MC2.MH MC3.49 MC3.155 MC3.156 MC3.159 MC3.160 MC3.161 MC3.163 MC3.164 MC3.165 MC3.167 MC3.169 MC3.170 MC3.MH MH1.1 MH2.1 MH3.1 MH4.1 MH5.1 Q3.3 Q3.4 Q3.5 QSFP1.0 QSFP2.0 U2.5 U2.6 U2.8 U4.17 U4.18 U4.19 U4.20 U4.21 U4.25 U4.26 U4.27 U4.28 U4.29 U4.30 U4.31 U4.32 U4.33 U9.6 U9.9 U10.6 U10.9 U13.12 U13.15 U13.16 U14.24 U18.1 U18.7 U18.9 U18.16 U18.17 U18.22 U18.26 U18.30 U18.31 U18.32 U18.33 U18.34 U18.39 U18.49 U18.50 U18.54 U18.55 U18.56 U18.64 U19.13 U19.27 U19.34 U19.41 U19.44 U19.48 U20.6 U20.7 U23.6 U23.9 U24.3 U24.14 Y1.2 Y1.4 Y3.2 Y3.4
copper on no net:
  other v1: 1633.86,98.43 2027.56,98.43
  other v2: 8395.29,3773.24 8407.1,3887.42 7643.32,3907.1 7643.23,3987.39 8383.48,4056.71 7513.4,4103.95 7566.39,4280.24

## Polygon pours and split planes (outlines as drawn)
DGND on L7-GND "L7_DGND" (solid, pour order 249): 19.68,19.68 19.68,5885.83 8838.58,5885.83 8838.58,19.68
DGND on L3-PWR "L8_DGND_2" (solid, pour order 263): 19.68,19.68 19.69,2633 446,2633 953.02,2125.98 1614.17,2125.98 1828.29,2340.1 2814.96,2340.1 2814.96,19.68
DGND on L3-PWR "L8_DGND_3" (solid, pour order 264): 1358.27,3179 1358.27,2523.62 922.38,2523.62 512.93,2933.07 19.68,2933.07 19.68,5885.83 767.72,5885.83 767.72,4527.56 1006,4289.28 1006,3523.62 1358.27,3523.62
VCCO_28 on L3-PWR "L8_VCCO_28" (solid, pour order 252): 6338.58,98.43 6338.58,1811.02 5374.02,2775.59 5374.02,5866.14 2283.46,5866.14 2283.46,3779.53 3937.01,3779.53 3937.01,1089 4729.9,1089 4970.28,848.62 4970.28,98.43
DGND on L3-PWR "L8_DGND_4" (solid, pour order 265): 3940.94,106.3 3940.94,1031.5 4716.54,1031.5 4921.26,826.77 4921.26,106.3
DGND on L3-PWR "L8_DGND_1" (solid, pour order 259): 8838.58,5885.83 8838.58,39.37 6377.95,39.37 6377.95,1830.71 5413.39,2795.28 5413.39,5885.83
VCCO_68 on L3-PWR "L3_VCCO_68" (solid, pour order 254): 1469.53,2480.36 2531,2480.13 2531,2271 2440.29,2271 1744.09,1574.8 594.49,1574.8 39.37,2129.92 39.37,2866.14 472.44,2866.14 858.22,2480.36
USB_VBUS on L3-PWR "L3_USB_VBUS" (solid, pour order 251): 6339.07,5594 6018,5594 5942,5518 5766.03,5518 5688.98,5440.94 5688.98,5177.17 5760.14,5106 6192.61,5106 6401.57,5314.96 6401.57,5531.5
VCCO_67 on L3-PWR "L8_VCCO_67" (solid, pour order 253): 3897.64,107 3897.64,1240.16 3897.64,3740.16 2244.09,3740.16 2244.09,5802 885.83,5802 885.83,4641.73 1468.5,4059.06 1468.5,3720.47 1403,3654.97 1403,2523.62 2860,2523.62 2860,107
VDDD on L3-PWR "L8_VDDD" (solid, pour order 258): 1371,4101.44 1371,3562.99 1076,3562.99 1076,4214 1258.44,4214
DGND on L8-SIG "L3_DGND_5" (solid, pour order 266): 19.68,19.68 19.68,1200.79 1515.75,1200.79 1515.75,826.77 2543.31,826.77 3129.92,240.16 3129.92,19.68
FT232_VCCD on L8-SIG "FT232_VCCD_L08_P300" (solid, pour order 300): 8437.01,4346.46 8507.87,4275.59 8507.87,3763.78 8393.7,3649.61 7775.59,3649.61 7688.98,3736.22 7688.98,4173.23 7862.2,4346.46
FT232_VREGIN on L8-SIG "FT232_VREGIN_L08_P299" (solid, pour order 299): 7848.05,4173.8 7858.22,4183.97 7921.58,4183.97 7970.09,4135.45 7970.09,4092.14 7942.99,4065.04 7871.67,4065.04 7848.05,4088.66
NetC13_2 on L8-SIG "NETC13_2_L08_P297" (solid, pour order 297): 8056.71,3899.23 8123.64,3899.23 8145.68,3877.18 8145.68,3783.48 8135.45,3773.24 8052.77,3773.24 8029.15,3796.87 8029.15,3875.61
NetC9_2 on L8-SIG "NETC9_2_L08_P298" (solid, pour order 298): 8174.33,3894.8 8234.88,3894.8 8269.35,3860.33 8269.31,3860.29 8269.31,3800.8 8241.75,3773.24 8170.88,3773.24 8163.01,3781.12 8163.01,3883.48
DGND on L8-SIG "L3_DGND_4" (solid, pour order 267): 5275.59,19.68 3622.05,19.68 3622.05,712.6 5177.17,712.6 5177.17,314.96 5275.59,216.54
DGND on L8-SIG "L8-SIG-DGND" (solid, pour order 301): 7925.2,393.7 7925.2,19.68 8838.58,19.68 8838.58,4803.15 7493.11,4803.15 7342.52,4652.56 7342.52,1700.79 6832.68,1700.79 6832.68,2625.98 6655.51,2803.15 6655.51,4043.31 3816.93,4043.31 3816.93,3925.2 4466.54,3275.59 4466.54,2952.76 4927.17,2952.76 6438.98,1440.95 6877.95,1440.95
DGND on L8-SIG "DGND_L08_P296" (solid, pour order 296): 5661.42,19.68 5661.42,720.47 5696.85,755.91 5696.85,1303.15 5771.65,1377.95 5885.83,1377.95 6177.17,1086.61 6177.17,834.65 6956.69,55.12 6956.69,19.68
DGND on L8-SIG "DGND_L08_P295" (solid, pour order 295): 23.62,2633.86 429.13,2633.86 763.78,2299.21 1681.1,2299.21 1681.1,2137.8 1157.48,1614.17 23.62,1614.17
DGND on L8-SIG "L3_DGND_1" (solid, pour order 260): 8838.58,5885.83 6460.63,5885.83 6460.63,5255.91 8224.41,5255.91 8496.06,5527.56 8838.58,5527.56
DGND on L8-SIG "L3_DGND_6" (solid, pour order 268): 2952.76,3838.58 3267.72,3523.62 3267.72,1594.49 4488.19,1594.49 4488.19,1850.39 3523.62,2814.96 3523.62,3464.57 3110.24,3877.95 2952.76,3877.95
+VDCIN on L8-SIG "L3_+VDCIN" (solid, pour order 238): 270,5409.45 270,3958.35 511.35,3717 2185.5,3717 2366.14,3897.64 2653.54,3897.64 2692.91,3937.01 2897.64,3937.01 2897.64,4610.24 2570.87,4937.01 1933.07,4937.01 1933.07,5169.29 1692.91,5409.45
VCCO_87_88 on L5-PWR "L5_VCCO_87_88" (solid, pour order 244): 39.37,944.88 216.54,944.88 216.54,1062.99 570.87,1417.32 6082.68,1417.32 7342.52,2677.17 7342.52,4035.43 7342.52,4637.8 7342.52,5031.5 6604.5,5031.5 4309.22,2736.22 39.37,2736.22
+3.3V_AUX on L5-PWR "L5_+3.3V_AUX" (solid, pour order 242): 39.37,39.37 8818.9,39.37 8818.9,5866.14 39.37,5866.14 39.37,2775.59 4315.59,2775.59 6591.18,5051.18 7366.14,5051.18 7366.14,4633.86 7366.14,4043.31 7366.14,2641.73 6102.36,1377.95 590.55,1377.95 255.91,1043.31 255.91,905.51 39.37,905.51
+1.1V_ETH on L5-PWR "+1.1V_ETH_L05_P241" (solid, pour order 241): 4161.42,4657.48 4271.65,4657.48 4307.09,4692.91 4393.7,4692.91 4393.7,4657.48 4448.82,4657.48 4606.3,4814.96 4606.3,4933.07 4622.05,4948.82 4649.61,4948.82 4665.35,4964.57 4665.35,5011.81 4649.61,5027.56 4625.98,5027.56 4610.24,5043.31 4610.24,5185.04 4555.12,5240.16 4555.12,5578.74 4519.69,5614.17 4220.47,5614.17 4122.05,5515.75 3921.26,5314.96 3921.26,4897.64
+2.5V_ETH on L5-PWR "+2.5V_ETH_L05_P239" (solid, pour order 239): 4618.11,5192.91 4618.11,5047.24 4629.92,5035.43 4653.54,5035.43 4673.23,5015.75 4673.23,4960.63 4653.54,4940.94 4625.98,4940.94 4614.17,4929.13 4614.17,4862.2 4791.34,4862.2 4811.02,4881.89 4811.02,5342.52 4740.16,5413.39 4740.16,5594.49 4720.47,5614.17 4602.36,5614.17 4566.93,5578.74 4566.93,5244.09
DGND on L10-BOT "NONET_L-01_P-001" (solid, pour order 290): 4122.05,5740.16 4736.22,5740.16 4771.65,5704.72 4771.65,5614.17 4716.54,5559.06 4145.67,5559.06 4086.61,5618.11 4086.61,5704.72
DGND on L10-BOT "NONET_L-01_P-001" (solid, pour order 274): 8441.93,1476.38 8780.51,1476.38 8780.51,952.76 8752.95,925.2 8563.98,925.2 8441.93,1047.24
DGND on L10-BOT "NONET_L-01_P-001" (solid, pour order 269): 1180.08,3946 1865,3946 1881,3930 1881,3728 1865,3712 1653,3712 1623,3682 897,3682 855,3724 855,3907 917,3969 1157.08,3969
DGND on L10-BOT "DGND_L10_P286" (solid, remove dead copper, pour order 286): 4188.98,5240.16 4578.74,5240.16 4578.74,4783.46 4527.56,4732.28 4204.72,4732.28 4133.86,4803.15 4133.86,5185.04
+5V_SZG on L6-PWR "L6_+5V_SZG" (solid, pour order 246): 7141.73,39.37 7141.73,669.29 1476.38,669.29 1476.38,3838.58 894.58,3838.58 864,3808 656,3808 572,3892 572,4140 708.66,4276.66 708.66,5433.07 3385.83,5433.07 3622.05,5669.29 3622.05,5866.14 39.37,5866.14 39.37,39.37
+1.8V on L6-PWR "L6_+1.8V_AUX" (solid, pour order 243): 2948.82,2354.33 2948.82,1232.28 8818.9,1232.28 8818.9,5866.14 6476.38,5866.14 6476.38,5078.74 5728.35,5078.74 5649.61,5161.42 5649.61,5295.28 5629.92,5314.96 5492.13,5314.96 5397.64,5409.45 4210.45,5409.45 3700.79,4899.79 3700.79,4212.6 6025.6,4212.6 6320.87,4507.87 6779.53,4507.87 6779.53,3464.57 7204.72,3464.57 7204.72,1610.24 7161.42,1566.93 6614.17,1566.93 6275.59,1908.9 6275.59,2354.33
VCCO_68 on L6-PWR "NONET_L-01_P-001" (solid, pour order 293): 2917.32,2500 2917.32,1208.66 8818.9,1208.66 8818.9,39.37 7165.35,39.37 7165.35,688.98 1515.75,688.98 1515.75,2500
+3.3V_QSFP on L6-PWR "L6_+3.3V_QSFP" (solid, pour order 237): 7187.01,2637.8 6606.3,2637.8 6287.4,2956.69 6287.4,3464.57 6740.16,3464.57 6740.16,4468.5 6339.5,4468.5 6044.23,4173.23 1515.75,4173.23 1515.75,2539.37 2948.82,2539.37 2948.82,2373.03 6275.59,2373.03 7187.01,2373.03
+5V_AUX on L6-PWR "L6_+5V_AUX" (solid, pour order 247): 843,3822 711,3822 615,3918 615,4123 748.03,4256.03 748.03,5393.7 3405.51,5393.7 3661.42,5649.61 3661.42,5866.14 6437.01,5866.14 6437.01,5118.11 5748.03,5118.11 5681.1,5185.04 5681.1,5314.96 5657.48,5338.58 5527.56,5338.58 5417.32,5448.82 4188.98,5448.82 3661.42,4921.26 3661.42,4212.6 1476.38,4212.6 1476.38,3877.95 898.95,3877.95
NetC178_2 on L6-PWR "L8_QSFP1_VCC1" (solid, pour order 272): 7054.16,1941.26 7054.16,1864.13 6693.94,1864.13 6484.25,2073.82 6484.25,2354.33 6665.35,2354.33 6665.35,2153.55 6877.64,1941.26
NetC180_2 on L6-PWR "NETC180_2_L06_P271" (solid, pour order 271): 7048.94,1950.88 7048.94,2006.43 7152.55,2006.43 7152.55,2226.91 7025.12,2354.33 6678.15,2354.33 6678.15,2158.58 6885.85,1950.88
NetC184_2 on L6-PWR "L8_QSFP1_VCCRX" (solid, pour order 270): 7053.16,1995.43 7274.6,1995.43 7274.6,1709.39 7149.94,1584.73 6626.88,1584.73 6303.15,1908.46 6303.15,2354.33 6473.43,2354.33 6473.43,2069.88 6679.21,1864.1 7002.95,1864.1 7053.16,1914.3
NetC53_2 on L6-PWR "L8_QSFP1_VCC1" (solid, pour order 285): 7054.17,3004.27 7054.17,2927.14 6693.94,2927.14 6484.26,3136.83 6484.26,3440.94 6665.36,3440.94 6665.36,3216.53 6877.62,3004.27
NetC55_2 on L6-PWR "NETC55_2_L06_P284" (solid, pour order 284): 7048.95,3013.89 7048.95,3069.44 7188.98,3069.44 7188.98,3440.94 6678.16,3440.94 6678.16,3221.59 6885.85,3013.89
NetC57_2 on L6-PWR "L8_QSFP1_VCCRX" (solid, pour order 283): 7053.17,3058.44 7188.98,3058.44 7188.98,2686.77 7155.75,2653.54 6621.09,2653.54 6303.16,2971.47 6303.16,3440.94 6473.43,3440.94 6473.43,3132.89 6679.22,2927.1 7002.96,2927.1 7053.17,2977.31
VCCO_28 on L1-TOP "VCCO_28_L01_P294" (solid, pour order 294): 5618.11,128.54 5720.47,128.54 5720.47,106.3 5653.35,39.17 5618.11,39.17
VCCO_67 on L1-TOP "VCCO_67_L01_P292" (solid, pour order 292): 1044.84,5776.78 942.48,5776.78 942.48,5799.02 1009.61,5866.15 1044.84,5866.15
VCCO_67 on L1-TOP "VCCO_67_L01_P291" (solid, pour order 291): 3570.87,128.54 3673.23,128.54 3673.23,106.3 3606.1,39.17 3570.87,39.17
NetC164_2 on L1-TOP "NETC164_2_L01_P289" (solid, pour order 289): 5456.69,5559.06 5472.44,5574.8 5472.44,5807.09 5527.56,5862.2 5602.36,5862.2 5602.36,5724.41 5594.49,5716.54 5553.15,5716.54 5547.24,5710.63 5547.24,5405.51 5503.94,5362.2 5228.35,5362.2 5192.91,5397.64 5192.91,5519.68 5232.28,5559.06
+5V_AUX on L1-TOP "+5V_AUX_L01_P288" (solid, pour order 288): 5692.91,5464.57 5692.91,5543.31 5669.29,5566.93 5669.29,5610.24 5748.03,5610.24 5775.59,5582.68 5775.59,5476.38 5763.78,5464.57
NetC55_2 on L1-TOP "NETC55_2_L01_P281" (solid, pour order 281): 6679.13,3528.54 6755.91,3528.54 6769.68,3514.76 6769.68,3388.78 6750,3369.09 6679.13,3369.09 6679.13,3425.2 6679.13,3487.2
NetC53_2 on L1-TOP "NETC53_2_L01_P280" (solid, pour order 280): 6540.35,3528.54 6617.13,3528.54 6630.91,3514.76 6630.91,3388.78 6611.22,3369.09 6540.35,3369.09 6540.35,3425.2 6540.35,3487.2
NetC57_2 on L1-TOP "NETC57_2_L01_P279" (solid, pour order 279): 6395.67,3528.54 6474.41,3528.54 6488.19,3514.76 6488.19,3388.78 6468.5,3369.09 6397.64,3369.09 6397.64,3425.2 6411.42,3438.98 6411.42,3473.43 6395.67,3489.17
+3.3V_QSFP on L1-TOP "+3.3V_QSFP_L01_P282" (solid, pour order 282): 6395.67,3560.04 6757.87,3560.04 6757.87,3608.27 6771.65,3622.05 6771.65,3682.09 6743.11,3710.63 6494.09,3710.63 6478.35,3694.88 6478.35,3646.65 6453.74,3622.05 6409.45,3622.05 6395.67,3608.27
+3.3V_QSFP on L1-TOP "+3.3V_QSFP_L01_P278" (solid, pour order 278): 6395.67,2497.05 6757.87,2497.05 6757.87,2545.28 6771.65,2559.06 6771.65,2619.09 6743.11,2647.64 6494.09,2647.64 6478.35,2631.89 6478.35,2583.66 6453.74,2559.06 6409.45,2559.06 6395.67,2545.28
NetC180_2 on L1-TOP "NETC180_2_L01_P277" (solid, pour order 277): 6679.13,2465.55 6755.91,2465.55 6769.69,2451.77 6769.69,2325.79 6750,2306.1 6679.13,2306.1 6679.13,2362.2 6679.13,2424.21
NetC178_2 on L1-TOP "NETC178_2_L01_P276" (solid, pour order 276): 6540.35,2465.55 6617.13,2465.55 6630.91,2451.77 6630.91,2325.79 6611.22,2306.1 6540.35,2306.1 6540.35,2362.2 6540.35,2424.21
NetC184_2 on L1-TOP "NETC184_2_L01_P275" (solid, pour order 275): 6395.67,2465.55 6474.41,2465.55 6488.19,2451.77 6488.19,2325.79 6468.5,2306.1 6397.64,2306.1 6397.64,2362.2 6411.42,2375.98 6411.42,2410.43 6395.67,2426.18
+VDCIN on L1-TOP "L1_+VDCIN" (solid, pour order 257): 2811.35,3941.61 2811.35,4161.09 2757.44,4215 2443.35,4215 2390.35,4162 2390.35,3941.61
+VDCIN on L1-TOP "+VDCIN_L01_P273" (solid, pour order 273): 425.2,5220.47 545.53,5220.47 675,5091 830,5091 849,5072 849,4946 694,4791 577,4791 543,4757 543,4271 510,4238 384,4238 347,4275 347,4874.56 389.76,4917.32 389.76,5185.04
USB_SHELL on L1-TOP "L1_USB_SHELL" (solid, pour order 255): 5834,5581.84 5834,5886.1 6356,5886.1 6356,5581.84 6268.16,5581.84 6250,5600 6250,5710 5947,5710 5947,5601 5927.84,5581.84
DGND on L2-GND "L2_DGND" (solid, pour order 240): 19.68,19.68 19.68,5885.83 8838.58,5885.83 8838.58,19.68
DGND on L4-GND "L4_DGND" (solid, pour order 248): 19.68,19.68 19.68,5885.83 8838.58,5885.83 8838.58,19.68
DGND on L9-GND "L9_DGND" (solid, pour order 250): 19.68,19.68 19.68,5885.83 8838.58,5885.83 8838.58,19.68

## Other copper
L1-TOP:
  region net NetC190_2: 2013,520 2162,520 2162,165 1357,165 1357,520 1455,520 1532,443 1936,443
  region net +2.5V_ETH: 4580.71,5647.64 4580.71,5594.09 4588.58,5586.22 4588.58,5554.72 4600.39,5542.91 4721.09,5542.91 4742.13,5563.95 4742.13,5629.53 4625.37,5629.53 4607.26,5647.64
  region net +1.1V_ETH: 4234.25,5647.64 4234.25,5594.09 4242.13,5586.22 4242.13,5554.72 4253.94,5542.91 4374.63,5542.91 4395.67,5563.95 4395.67,5629.53 4278.91,5629.53 4260.8,5647.64
  region net DGND: 4383.86,5645.7 4383.86,5718.86 4311.62,5718.86 4279.26,5686.5 4185.54,5686.5 4181.1,5690.94 4181.1,5725.59 4174.97,5725.59 4169.89,5730.67 4169.89,5760.05 4174.21,5764.37 4220.47,5764.37 4220.47,5816.96 4222.02,5818.5 4127.8,5818.5 4108.27,5798.97 4108.27,5643.31 4147.64,5643.31 4164.14,5659.81 4269.92,5659.81 4284.45,5645.28 4329.72,5645.28
  region net +3.3V_AUX: 4234.25,5700.1 4234.25,5830.31 4294.33,5830.31 4294.33,5721.26 4273.18,5700.1
  region net DGND: 4730.32,5645.7 4730.32,5718.86 4658.08,5718.86 4625.72,5686.5 4532,5686.5 4527.56,5690.94 4527.56,5725.59 4521.43,5725.59 4516.35,5730.67 4516.35,5760.05 4520.67,5764.37 4566.93,5764.37 4566.93,5816.96 4568.47,5818.5 4474.26,5818.5 4454.72,5798.97 4454.72,5643.31 4494.09,5643.31 4510.6,5659.81 4616.37,5659.81 4630.91,5645.28 4676.18,5645.28
  region net +3.3V_AUX: 4580.71,5700.1 4580.71,5830.31 4640.79,5830.31 4640.79,5721.26 4619.64,5700.1
  region net NetC139_2: 1228.58,3852.14 1193.08,3852.14 1142.58,3902.64 983.19,3902.64 956.69,3929.13 929.13,3929.13 929.13,4086.61 1011.81,4086.61 1035.58,4062.84 1035.58,3938.14 1042.72,3931 1131.75,3931 1200.61,3862.14 1228.58,3862.14
  region net NetC118_2: 1465.58,3783.64 1498.58,3783.64 1545.58,3736.64 1627.36,3736.64 1648,3716 1648,3396.64 1569.5,3396.64 1569.5,3649.5 1540.58,3678.42 1540.58,3699.64 1531.08,3709.14 1519.08,3709.14 1494.58,3733.64 1465.58,3733.64
  region net +5V_AUX: 633,4069.73 633,3900 759,3900 759,3821 854.33,3821 854.33,3901.57 874.02,3921.26 874.02,4086.61 746,4086.61 729.12,4069.73
  region net +5V_SZG: 625,3562.27 625,3738 759,3738 759,3812 854.33,3812 854.33,3732.28 874.02,3712.6 874.02,3543.31 748.08,3543.31 729.12,3562.27
  region net DGND: 968.86,3887.14 956,3900 885.86,3900 885.86,3732.98 938.43,3732.98 980.58,3775.14 1055.58,3775.14 1055.58,3850.14 1067.58,3862.14 1105.58,3862.14 1105.58,3887.14
  region net +VDCIN: 1069.58,3773.64 1146.58,3773.64 1185.08,3812.14 1227.58,3812.14 1227.58,3843.14 1186.58,3843.14 1142.58,3887.14 1117.58,3887.14 1117.58,3848.14 1069.58,3848.14
  region net NetC149_2: 1227.58,3803.14 1189.58,3803.14 1147.58,3761.14 989.48,3761.14 929.13,3700.79 929.13,3543.31 1011.81,3543.31 1036.58,3568.08 1036.58,3719.64 1044.94,3728 1134.95,3728 1200.08,3793.14 1227.58,3793.14
  region net +VDCIN: 1237.57,4128.5 1308.43,4128.5 1308.43,4077.43 1289,4058 1289,4007.86 1286.32,4005.17 1265.84,4005.17 1265.84,4021.16 1237.57,4049.43 1237.57,4077.32
  region net USB_VBUS: 5813.98,5415.35 5813.98,5321.85 5794.13,5302 5705.87,5302 5692.91,5314.96 5692.91,5401.57 5706.69,5415.35
  region net +3.3V_AUX: 1664,3920.64 1664,4260.64 1877,4260.64 1877,3920.64
  region net NetC126_2: 1465.58,3871.64 1537.58,3871.64 1537.58,3909.64 1551.58,3923.64 1648,3923.64 1648,4260.64 1568.91,4260.64 1568.91,4031.91 1537.58,4000.58 1537.58,3966.64 1492.58,3921.64 1465.58,3921.64
  region net DGND: 1426.53,3862.64 1548.58,3862.64 1548.58,3909.64 1633.58,3909.64 1877,3909.64 1877,3738.64 1662.36,3738.64 1632.58,3768.42 1632.58,3832.64 1426.53,3832.64 1426.53,3747.64 1266.58,3747.64 1266.58,3906.64 1426.53,3906.64
  region net +VDCIN: 1465.58,3822.64 1494.58,3822.64 1496.58,3820.64 1618.58,3820.64 1618.58,3745.64 1546.58,3745.64 1499.58,3792.64 1465.58,3792.64
  region net +3.3V_QSFP: 1664,3726.64 1877,3726.64 1877,3396.64 1664,3396.64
